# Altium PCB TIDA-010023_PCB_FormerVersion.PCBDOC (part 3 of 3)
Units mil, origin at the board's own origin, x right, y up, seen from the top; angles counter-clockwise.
Board outline 4724.44 x 3937.01 mil, 2 copper layers (Top Layer, Bottom Layer), stack 62 mil thick; 263 components, 126 nets, 611 pads, 186 vias.
Unrouted connection lines stored in the file: 58.
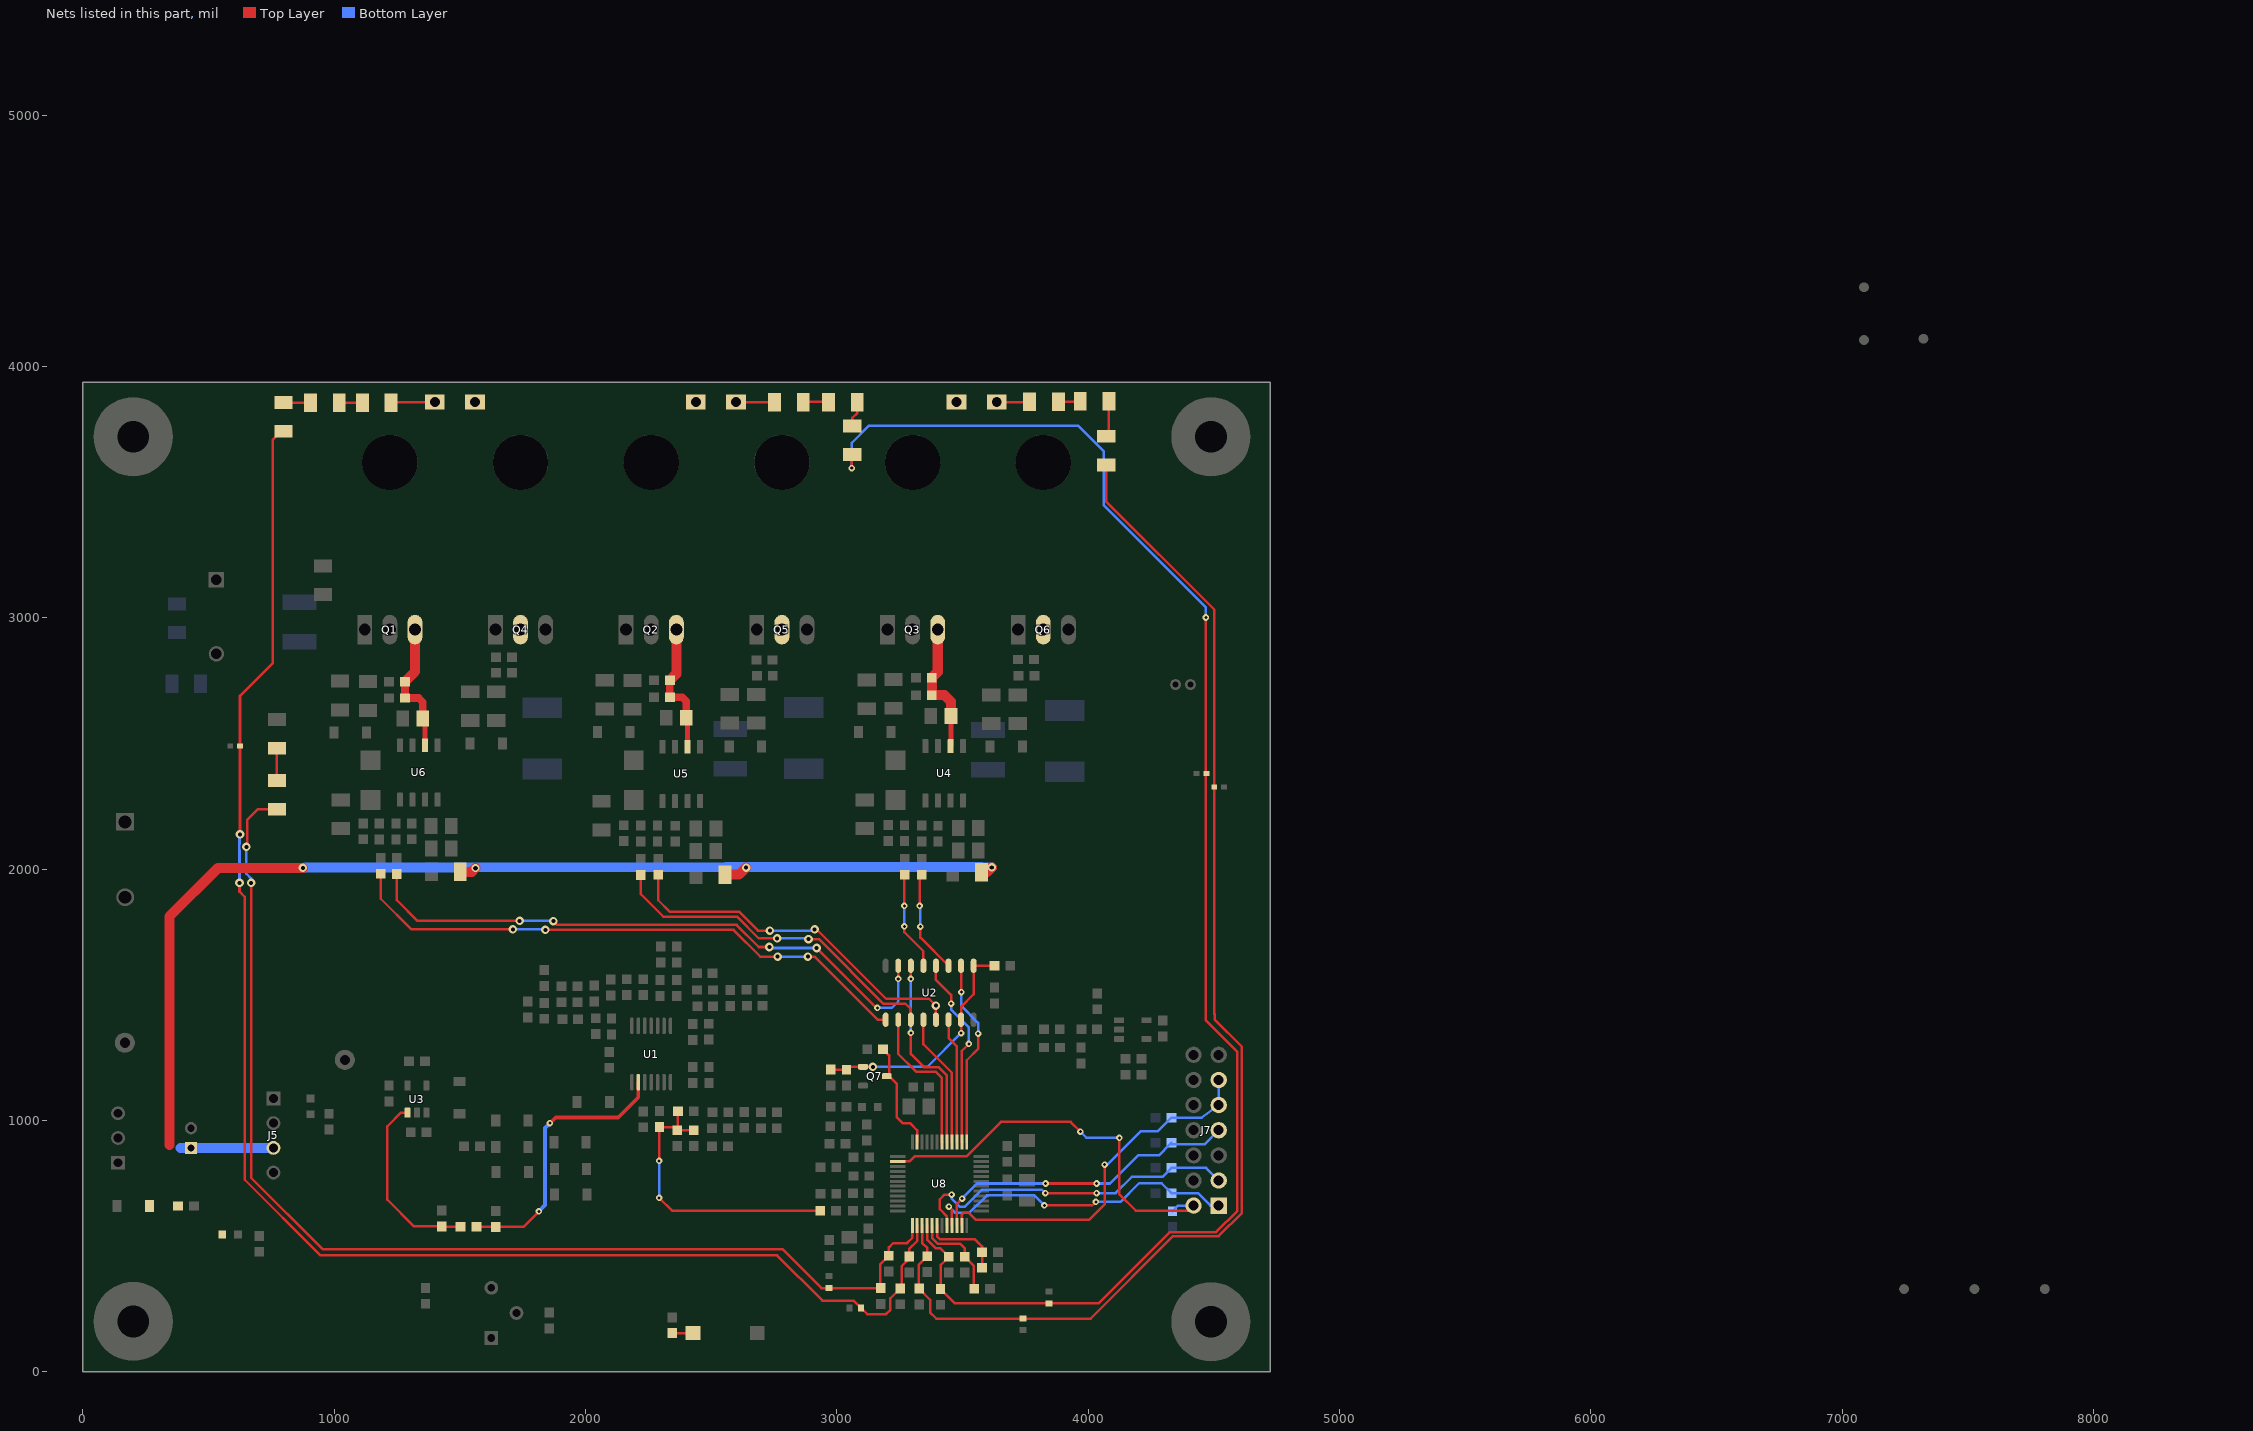
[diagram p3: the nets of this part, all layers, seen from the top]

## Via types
v1: diameter 26, hole 12, Top Layer to Bottom Layer, 157 vias
v2: diameter 34, hole 16, Top Layer to Bottom Layer, 28 vias
v3: diameter 32, hole 18, Top Layer to Bottom Layer, 1 vias

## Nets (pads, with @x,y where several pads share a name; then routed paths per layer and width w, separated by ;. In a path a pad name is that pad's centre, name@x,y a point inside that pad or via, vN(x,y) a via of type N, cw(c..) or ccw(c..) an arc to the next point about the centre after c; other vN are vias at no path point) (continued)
NetR92_1: R92.1 R96.2 | length 87.2
  Top Layer w10: R92.1@3881.09,3860 3966.91,3860 R96.2@3967.91,3861
NetR93_1: R93.1 R97.2 | length 100.8
  Top Layer w10: R93.1@2868.09,3859 R97.2@2968.91,3859
NetR94_1: R94.1 R98.2 | length 92.2
  Top Layer w10: R98.2@1021.09,3856 R94.1@1111.91,3856
  Top Layer w15: R98.2@1020.09,3855 R98.2@1021.09,3856
NetR95_1: R95.1 R105.2 | length 128.8
  Top Layer w10: R105.2@772,2352.09 R95.1@772,2480.91
NetR96_1: R96.1 R104.2 | length 145.5
  Top Layer w10: R96.1@4082.09,3861 4082.09,3726.17 4081,3725.09 R104.2@4090.09,3725.09
NetR97_1: R97.1 R106.2 | length 103.2
  Top Layer w10: R106.2@3061,3763.09 3061,3795 3081.09,3815.09 R97.1@3081.09,3858
NetR98_1: R98.1 R107.2 | length 108.4
  Top Layer w10: R107.2@799.09,3855 R98.1@905.91,3855
  Top Layer w15: R107.2@798,3856.09 R107.2@799.09,3855
OC: C9.1 Q7.1 R8.2 R118.2 U2.1 U2.15 | length 951.3
  Top Layer w10: R8.2@2975,1202.5 3037,1202.5 C9.1@3038,1201.5 3049.91,1213.4 Q7.1@3103.76,1213.4 v2(3143.4,1213.4) ; v1(3494,1347) U2.15@3494,1400.72 3494,1452 3544,1502 U2.1@3544,1615.28 3626.22,1615.28 R118.2@3626.5,1615
  Bottom Layer w10: v2(3143.4,1213.4) 3360.4,1213.4 v1(3494,1347)
OC_TZ: Q7.3 R119.2 U8.47 | length 456.2
  Top Layer w10: R119.2@3183.5,1283 3208,1258.5 3208,1185.76 Q7.3@3198.24,1176 3208,1176 3239,1145 3239,1012 3263,988 3292,988 3319.5,960.5 U8.47@3319.5,913.9
PHASE_A: C40.2 C41.2 J1.1 J1.2 Q1.3 Q4.2 R64.1 R94.2 U6.6 | length 713.4
  Top Layer w10: R94.2@1228.35,3858.27 J1.2@1400.16,3858.27
  Top Layer w20: C41.2@1352.52,2599.6 1361.52,2590.6 U6.6@1361.52,2492.87
  Top Layer w30: C40.2@1281.5,2745.7 R64.1@1281.5,2680.7 1336.3,2680.7 1352.52,2664.48 C41.2@1352.52,2599.6
  Top Layer w40: C40.2@1281.5,2745.7 1321.18,2785.39 Q1.3@1321.18,2952.76
PHASE_B: C33.2 C34.2 J2.1 J2.2 Q2.3 Q5.2 R49.1 R93.2 U5.6 | length 687.9
  Top Layer w10: J2.1@2598.43,3858.27 R93.2@2751.65,3858.27
  Top Layer w20: C34.2@2401,2602 2406,2597 U5.6@2406,2486.87
  Top Layer w30: R49.1@2335.5,2751 C33.2@2335.5,2683 2385,2683 2401,2667 C34.2@2401,2602
  Top Layer w40: R49.1@2335.5,2751 2361.18,2776.69 Q2.3@2361.18,2952.76
PHASE_C: C27.2 C28.2 J3.1 J3.2 Q3.3 Q6.2 R34.1 R92.2 U4.6 | length 667
  Top Layer w10: J3.1@3636,3858.27 R92.2@3765.18,3858.27
  Top Layer w15: R92.2@3765.18,3858.27 R92.2@3766.91,3860
  Top Layer w20: U4.6@3452,2489.27 3454,2491.27 C28.2@3454,2609
  Top Layer w40: Q3.3@3401.18,2952.76 3401.18,2784.69 C27.2@3377.5,2761 R34.1@3377.5,2692 3428,2692 3454,2666 C28.2@3454,2609
PWM_A_BOT: R65.1 U2.9 | length 2339.6
  Top Layer w10: R65.1@1185,1981.5 1185,1882 1307,1760 v2(1711,1760) ; v2(1840,1758) 2589,1758 2695,1652 v2(2764,1652) ; v2(2884,1652) 2911,1652 3162,1401 U2.9@3193.72,1401 ; U2.9@3190.72,1398 U2.9@3193.72,1401 ; U2.9@3194,1400.72 U2.9@3193.72,1401
  Bottom Layer w10: v2(1711,1760) 1838,1760 v2(1840,1758) ; v2(2764,1652) 2880,1652 2889,1643 2894,1648 2890,1652 v2(2884,1652)
PWM_A_TOP: R71.1 U2.7 | length 2430.4
  Top Layer w10: R71.1@1248,1979.5 R71.1@1249,1980.5 1249,1876 1331,1794 v2(1738,1794) ; v2(1872,1793) 1887,1778 2601,1778 2689,1690 v2(2731,1690) ; v2(2919,1686) 3157,1448 v1(3161,1448) ; v1(3244,1563) U2.7@3244,1615.28
  Bottom Layer w10: v2(1738,1794) 1871,1794 v2(1872,1793) ; v2(2731,1690) 2735,1686 v2(2919,1686) ; v1(3161,1448) 3218.3,1448 3244,1473.7 v1(3244,1563)
PWM_B_BOT: R50.1 U2.11 | length 1370.2
  Top Layer w10: R50.1@2220,1976.5 2220,1900 2309,1811 2602,1811 2689,1724 v2(2762,1724) ; v2(2887,1721) 2928,1721 3184,1465 3272,1465 3294,1443 U2.11@3294,1400.72
  Bottom Layer w10: v2(2762,1724) v2@2876.36,1724
PWM_B_TOP: R54.1 U2.13 | length 1449.1
  Top Layer w10: R54.1@2289,1977.5 2289,1876 2334,1831 2610,1831 2686,1755 v2(2733,1755) ; v2@2911,1768.63 v2(2911,1760) 2919.63,1760 3195.63,1484 3367,1484 v2(3394,1457) U2.13@3394,1400.72
  Bottom Layer w10: v2(2733,1755) 2906,1755 v2(2911,1760)
PWM_C_BOT: R35.1 U2.5 | length 394.5
  Top Layer w10: v1(3268,1772) 3268,1749 3344,1673 U2.5@3344,1615.28 ; v1(3268,1854) 3268,1975.5 R35.1@3270,1977.5
  Bottom Layer w10: v1(3268,1772) v1(3268,1854)
PWM_C_TOP: R36.1 U2.3 | length 413.2
  Top Layer w10: v1(3329,1854) 3329,1969.5 R36.1@3337,1977.5 ; v1(3332,1771) 3332,1727.28 U2.3@3444,1615.28
  Bottom Layer w10: v1(3329,1854) 3332,1851 v1(3332,1771)
RESET: R87.1 S1.1 | length 82.3
  Top Layer w10: R87.1@2345,153.5 2426.55,153.5 S1.1@2427.05,154
S_PWM_A_BOT: U2.10 U8.42 | length 606
  Top Layer w10: U2.10@3244,1400.72 3244,1265 3315,1194 3393,1194 3418,1169 U8.42@3418,913.9 U8.42@3419,914.9
S_PWM_A_TOP: U2.6 U8.41 | length 794.9
  Top Layer w10: v1(3294,1348) 3294,1264 3346,1212 3404,1212 3437.7,1178.3 U8.41@3437.7,913.9 ; v1(3294,1563) U2.6@3294,1615.28
  Bottom Layer w10: v1(3294,1348) v1(3294,1563)
S_PWM_B_BOT: U2.12 U8.40 | length 533.8
  Top Layer w10: U2.12@3344,1400.72 3344,1303 3457.4,1189.6 U8.40@3457.4,913.9
S_PWM_B_TOP: U2.14 U8.39 | length 500.5
  Top Layer w10: U2.14@3444,1400.72 3444,1328 3477.1,1294.9 U8.39@3477.1,913.9
S_PWM_C_BOT: U2.4 U8.38 | length 769
  Top Layer w10: U2.4@3394,1615.28 3394,1559 3454,1499 v1(3454,1465) ; U8.38@3498,915.1 U8.38@3496.8,913.9 3496.8,1276.8 v1(3525,1305)
  Bottom Layer w10: v1(3454,1465) 3454,1440.72 3525,1369.72 v1(3525,1305)
S_PWM_C_TOP: U2.2 U8.37 | length 748.4
  Top Layer w10: U2.2@3494,1615.28 3495,1614.28 v1(3495,1510) ; U8.37@3516.5,913.9 3516.5,1239.5 3562,1285 v1(3562,1345)
  Bottom Layer w10: v1(3495,1510) 3495,1455 3562,1388 v1(3562,1345)
Speed_Ref: C51.2 R79.2 U8.17 | length 372.1
  Top Layer w10: U8.17@3378.6,582 3378.6,532.4 3401,510 3489,510 3509,490 R79.2@3509,457.5 3544,422.5 3544,333.5 C51.2@3546.5,331
TCK: J7.9 J7.11 R102.1 U8.23 | length 1474.6
  Top Layer w10: U8.23@3496.8,582 3496.8,623.8 3506,633 3524,633 3553,604 4003,604 4065,666 v1(4065,824)
  Bottom Layer w10: v1(4065,824) 4076,824 4208,956 4275.89,956 R102.1@4330.89,1011 4452,1011 J7.9@4519,1061 ; J7.9@4502,1061 J7.9@4519,1061 ; J7.11@4519,1161 J7.9@4519,1061
TDI: J7.3 R100.1 U8.20 | length 1359.9
  Top Layer w10: U8.20@3437.7,582 3437.7,618.36 3409,647.06 3409,686 3428,705 v1(3456,705) ; v1(3829,711) v1(4033,711)
  Bottom Layer w10: v1(3456,705) 3456,689 3489,656 3508,656 3577,725 3815,725 v1(3829,711) ; v1(4033,711) 4109,711 4173,775 4294.89,775 R100.1@4330.89,811 4469,811 J7.3@4519,761
TDO: J7.7 R101.1 U8.22 | length 1256.2
  Top Layer w10: U8.22@3477.1,582 3477.1,668.1 v1(3498,689) ; v1(3830,749) v1(4033,749)
  Bottom Layer w10: v1(3498,689) 3558,749 v1(3830,749) ; v1(4033,749) 4086,749 4198,861 4280.89,861 R101.1@4326,906.11 ; R101.1@4330.89,911 R101.1@4326,906.11 ; J7.7@4519,961 4464.11,906.11 R101.1@4326,906.11
TEMP_SENSE: C44.2 R68.2 U8.18 | length 323.7
  Top Layer w10: U8.18@3398.3,582 3398.3,538.7 3409,528 3548,528 3577.5,498.5 C44.2@3577.5,475 R68.2@3577.5,414
TH+: R18.1 R19.2 U1.9 | length 1098
  Top Layer w10: R19.2@1565.5,577 1565.99,576.5 R18.1@1643,576.5 1752.5,576.5 v1(1814,638)
  Top Layer w15: v1(1858,989) 1881,1012 2130,1012 2209.8,1091.8 U1.9@2209.8,1152
  Bottom Layer w15: v1(1814,638) 1839,663 1839,970 v1(1858,989)
TH-: R19.1 R20.2 U3.1 | length 730.6
  Top Layer w10: U3.1@1291.6,1030.87 1265.87,1030.87 1211,976 1211,685 1317.5,578.5 R20.2@1428,578.5 1429.5,577 R19.1@1502.5,577
TMS: J7.1 R99.1 U8.21 | length 1282.5
  Top Layer w10: v1(3445,657) 3457.4,644.6 U8.21@3457.4,582 ; v1(3825.64,662) 4016,662 v1(4030,676)
  Bottom Layer w10: v1(3445,657) 3469,633 3527.79,633 3596.79,702 3785.64,702 v1(3825.64,662) ; v1(4030,676) 4128,676 4202,750 4291.89,750 R99.1@4330.89,711 4436,711 4486,661 J7.1@4519,661
TRST: J7.2 R103.1 U8.2 | length 1621.7
  Top Layer w10: U8.2@3242.1,836.7 3288.7,836.7 3309,857 3515,857 3652,994 3930,994 v1(3969,955) ; v1(4124,931) 4124,706 4189,641 4399,641 J7.2@4419,661
  Bottom Layer w10: v1(3969,955) 3993,931 v1(4124,931) ; R103.1@4335,638.5 4357.5,661 J7.2@4419,661
VA_FB: C64.1 D25.2 R107.1 R111.2 U8.14 U9.1 | length 6244.5
  Top Layer w10: v2(623,1945) 623,1910 644,1889 644,764 944,464 2122,464 2123,463 2762,463 2942,283 3066.62,283 D25.2@3096.62,253 3120.62,229 3196,229 3213,246 3213,292.5 R111.2@3252,331.5 ; v2(625,2138) 625,2689 755.46,2819.46 755.46,3708.46 788.91,3741.91 R107.1@798,3741.91 ; R111.2@3250,331.5 3257.3,338.8 3257.3,419.75 3287,449.45 C64.1@3287,458.5 3287,488 3319.5,520.5 U8.14@3319.5,582 U8.14@3320,581.5
  Bottom Layer w10: v2(623,1945) 623,2075.4 622,2076.4 622,2099.6 623,2100.6 623,2136 v2(625,2138)
VB_FB: C63.1 D24.2 R106.1 R110.2 U8.16 U10.1 | length 6140.2
  Top Layer w10: v1@3058,3594 v1(3059,3595) 3059,3646.91 R106.1@3061,3648.91 ; U8.16@3358.9,582 3358.9,526.1 3394,491 3411.5,491 C63.1@3445,457.5 3413,425.5 3413,330.5 R110.2@3412,329.5 3468.5,273 4042,273 4325,556 4509,556 4593,640 4593,1273 4468,1398 v1(4468,3001)
  Bottom Layer w10: v1(3059,3595) 3059,3696 3126,3763 3961,3763 4061,3663 4061,3448 4468,3041 v1(4468,3001)
VC_FB: C62.1 D23.2 R104.1 R109.2 U8.15 U11.1 | length 5012.5
  Top Layer w10: U8.15@3339.2,582 3339.2,512.8 3360,492 C62.1@3360,459.5 3325,424.5 3325,332.5 R109.2@3327,330.5 3371,286.5 3371,236 3396,211 4009,211 4338,540 4519,540 4611,632 4611,1293 4502.5,1401.5 4502.5,1423 4502.18,1423.32 4502.18,1485 4501.31,1485.87 U11.1@4501.31,2326 4501.31,3032.69 4071,3463 R104.1@4071,3607.91
VCC_15V: C59.1 C60.1 D18.2 D21.1 J5.3 R32.2 R42.2 R61.2 | length 4837.5
  Top Layer w40: 343.92,901.98 343.92,1810.92 538,2005 v2(875,2005) ; R61.2@1501.09,1989 1547,1989 v3(1562,2004) ; R42.2@2554.09,1978 2611,1978 v2(2639,2006) ; R32.2@3575.09,1987 3596,1987 v2(3616,2007)
  Bottom Layer w40: 387.76,890.24 C59.1@430,890.24 757.45,890.24 J5.3@758,890.79 ; v2@883,2006 1519,2006.71 1562,2006.76 2558,2007.87 2639,2007.96 3575,2009 3577,2007 v2(3616,2007)
VDC_FB: C61.1 D22.2 R105.1 R108.2 U8.13 | length 4592
  Top Layer w10: v2(650,2088) 653,2091 653,2196 694.91,2237.91 R105.1@772,2237.91 ; v2(669,1945) 669,772 953.34,487.66 2783.34,487.66 2938.5,332.5 R108.2@3174,332.5 3172,334.5 3172,426.5 C61.1@3207,461.5 3207,495 3224,512 3279,512 3299.8,532.8 U8.13@3299.8,582
  Bottom Layer w10: v2(650,2088) 650,1982 669,1963 v2(669,1945)
VREF: C18.1 R23.1 R24.2 R25.1 R120.1 | length 1163.5
  Top Layer w10: v1(2293,692) 2345,640 R120.1@2933.5,640 ; v1(2293,839.33) 2293,972.72 R23.1@2293.98,973.7 2356.98,973.7 C18.1@2367.49,963.2 ; R25.1@2367.49,1036.2 C18.1@2367.49,963.2 ; R24.2@2429.98,960.7 C18.1@2364.98,960.7 C18.1@2367.49,963.2
  Bottom Layer w10: v1(2293,692) v1(2293,839.33)
pads on no net: FID1.1 FID2.1 FID3.1 FID4.1 FID5.1 FID6.1 H1.1 H2.1 H3.1 H4.1 H11.0 H12.0 H13.0 H14.0 J5.4 J6.3 J7.6 J7.13 J7.14 U8.1 U8.4 U8.8 U8.9 U8.19 U8.24 U8.25 U8.26 U8.27 U8.28 U8.29 U8.30 U8.31 U8.36 U8.45 U8.46

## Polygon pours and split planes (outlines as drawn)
PHASE_C on Top Layer "TOP_LAYER_PHASE_C_P062" (solid, remove dead copper, pour order 62): 3388,2900 3420,2900 3539,2900 3554,2915 3554,3124 3579,3149 3751,3149 3791,3109 3791,2916 3810,2897 3833,2897 3850,2914 3850,3322 3849,3322 3678,3493 3680,3495 3680,3887 3438,3887 3437,3886 3437,3054 3371,2988 3371,2917
PHASE_B on Top Layer "TOP_LAYER_PHASE_B_P060" (solid, remove dead copper, pour order 60): 2348,2903 2380,2903 2499,2903 2514,2918 2514,3127 2539,3152 2711,3152 2751,3112 2751,2919 2770,2900 2793,2900 2810,2917 2810,3325 2809,3325 2638,3496 2640,3498 2640,3890 2398,3890 2397,3889 2397,3057 2331,2991 2331,2920
PHASE_A on Top Layer "TOP_LAYER_PHASE_A_P058" (solid, remove dead copper, pour order 58): 1309,2901 1341,2901 1460,2901 1475,2916 1475,3125 1500,3150 1672,3150 1712,3110 1712,2917 1731,2898 1754,2898 1771,2915 1771,3323 1770,3323 1599,3494 1601,3496 1601,3888 1359,3888 1358,3887 1358,3055 1292,2989 1292,2918
VCC_15V on Top Layer "Top Layer-No Net 2" (solid, pour order 44): 459.19,914.69 459.19,772.19 397,710 397,633.69 348.61,633.69 246.19,633.69 246.19,894.69 266.19,914.69
PHASE_A on Top Layer "Top Layer-No Net 1" (solid, pour order 36): 1587,3507 1771,3323 1771,3161 1760,3161 1587,3334
NetQ6_3 on Bottom Layer "BOTTOM_LAYER_NETQ6_3_P078" (solid, remove dead copper, pour order 78): 3828,2590 3986,2590 4014,2618 4013.82,2984.18 3999,2999 3911,2999 3891,2979 3891,2805 3828,2742
NetQ5_3 on Bottom Layer "BOTTOM_LAYER_NETQ5_3_P076" (solid, remove dead copper, pour order 76): 2789,2601 2947,2601 2975,2629 2974.82,2995.18 2960,3010 2872,3010 2852,2990 2852,2816 2789,2753
+VDC on Bottom Layer "Bottom Layer-No Net 2" (solid, remove dead copper, pour order 74): 101,2153 232,2153 246,2167 246,2955 321,3030 931,3030 1027,3126 1027,3166 1053,3192 1153,3192 1195,3150 1250,3150 1288,3188 2189,3188 2232,3145 2291,3145 2330,3184 2488,3184 2501,3171 2541,3171 2554,3184 3222,3184 3270,3136 3330,3136 3383,3189 3508,3189 3533,3164 3573,3164 3593,3184 3593,3392 3571,3414 507,3414 429,3336 429,3335 209,3335 88,3214 87,3214 87,2167
AGND on Bottom Layer "Bottom Layer-No Net 2" (solid, remove dead copper, pour order 70): 84,1800 96,1788 380,1788 536,1944 536,2381 573,2418 705,2418 982,2141 3912.16,2141 3999,2227.84 3999,2417 3986,2430 3824,2430 3789,2395 3699.93,2395 3666.93,2428 3534.07,2428 3502,2395.93 3502,2395 2993,2395 2946,2442 2791,2442 2744,2395 2677.93,2395 2641.93,2431 2641.93,2432 2508.07,2432 2508.07,2431.07 2472,2395 1951,2395 1905,2441 1749,2441 1703,2395 1159,2395 928.93,2625.07 928.93,2940.07 914,2951 910,2951 551,2951 442.45,2842.45 442.45,2664 358,2579.55 358,2043 305,1990 95,1990 84,1979
NetQ4_3 on Bottom Layer "BOTTOM_LAYER_NETQ4_3_P066" (solid, remove dead copper, pour order 66): 1749,2601 1907,2601 1935,2629 1934.82,2995.18 1920,3010 1832,3010 1812,2990 1812,2816 1749,2753

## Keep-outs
Keep-Out Layer:
  circle w10: c200,3720.47 r293.13
  circle w10: c4488.19,3720.47 r315.73
  circle w10: c4488.19,199 r305.93
  circle w10: c204,193 r375.59
  text ".Layer_Name" at 577,-858.49 h60

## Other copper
Top Layer:
  rectangle net NetD21_2: 51,634 167,860
  text ".Layer_Name" at 577,-858.49 h60
Bottom Layer:
  pour cut-out: 2946,2602 2946,2603 2977.82,2634.82 2977.82,2602
  pour cut-out: 910,2951 918,2951 914,2955
  text ".Layer_Name" at 577,-858.49 h60

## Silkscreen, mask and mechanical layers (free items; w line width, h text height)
Top Overlay:
  region: 982,185 682,185 682,85 982,85
  lines w10: 834,1921 1004,1921 1087.8,2090.02 ; 1751,1355 1876.02,1442.8 ; 1870,1924 2053,1924 2124.1,2083.02 ; 2244,1669 2268.78,1587.18 ; 2390.27,1586.98 2416,1658 ; 2520,1426 2532,1412 ; 2534.98,1546.2 2563,1660 ; 2594.96,993 2601,1120 ; 2937,1925 3118,1925 3176.8,2084.02
  text "TIDA-010023.PCB_Rev-1" at 513,213 h78.74
  text ".Layer_Name" at 577,-858.49 h60
Bottom Overlay:
  text ".Layer_Name" at 577,-858.49 h60
Top Paste:
  text ".Layer_Name" at 577,-858.49 h60
Bottom Paste:
  text ".Layer_Name" at 577,-858.49 h60
Top Solder:
  text ".Layer_Name" at 577,-858.49 h60
  text ".Layer_Name" at 577,-858.49 h60
Bottom Solder:
  region: 84,1800 96,1788 380,1788 536,1944 536,2381 573,2418 705,2418 982,2141 3912.16,2141 3999,2227.84 3999,2417 3986,2430 3824,2430 3789,2395 3699.93,2395 3666.93,2428 3534.07,2428 3534.07,2427.07 3502,2395 1159,2395 928.93,2625.07 928.93,2940.07 918,2951 551,2951 442.45,2842.45 442.45,2664 358,2579.55 358,2043 305,1990 95,1990 84,1979
  region: 3270,2952 3331,2952 3331,3135 3385,3189 3219,3189 3271,3137 3271,2951
  region: 2231,2950 2292,2950 2292,3144 2291,3145 2341,3195 2341,3213 2189,3213 2187,3211 2189,3209 2189,3188 2232,3145 2231,3144
  region: 1190,2949 1252,2949 1250,2951 1250,3150 1288,3188 1288,3231 1154,3231 1156,3229 1156,3188 1191,3153 1190,3152
  region: 87,2167 101,2153 232,2153 246,2167 246,2955 321,3030 931,3030 1027,3126 1027,3166 1050,3189 1056,3189 3593,3189 3593,3392 3571,3414 507,3414 429,3336 429,3335 209,3335 88,3214 87,3214
  text ".Layer_Name" at 577,-858.49 h60
Drill Guide:
  text ".Layer_Name" at 577,-858.49 h60
M1 Board Outline:
  the board outline again, w10
  text ".Layer_Name" at 577,-858.49 h60
M2 Board Dimensions:
  rectangle: 125,-400 500,-275
  rectangle: 0,-275 125,-150
  lines w7: 0,-275 1000,-275 ; 125,-400 125,-150 ; 250,-400 250,-150 ; 500,-400 500,-150 ; 750,-400 750,-150 ; 0,-400 0,-150 1000,-150 1000,-400 0,-400
  text ".Layer_Name" at 577,-858.49 h60
M3 3D STEP Top:
  text ".Layer_Name" at 577,-858.49 h60
M4 3D STEP Bottom:
  text ".Layer_Name" at 577,-858.49 h60
M5 Assembly Top:
  lines w10: -292,-930.17 6308,-930.17 ; -292,-726.83 6310,-726.83 ; -292,-523.5 -292,-1133.5 3713,-1133.5 6310,-1133.5 6310,-523.5 -291.5,-523.5 -291.5,-1133.5 1284,-1133.5 ; 2173,-1133.5 2173,-523.5 ; 3440,-726.83 3440,-523.5 ; 4280,-726.83 4280,-523.5 ; 4902,-1140 4902,-937.17
  text "COMPONENTS MARKED 'DNP' SHOULD NOT BE POPULATED." at 1153.5,-318.5 h60
  text "ASSEMBLY VARIANT:" at 1153,-434 h60
  text ".VariantName" at 2189,-434 h60
  text "PCB VIEWED FROM TOP SIDE" at -228.5,-655.67 h60
  text "BOARD #:" at 2248,-655.67 h60
  text ".PRJ_Number" at 2793.5,-655.67 h60
  text "REV:" at 3638,-655.67 h60
  text ".PCB_Rev" at 3929.5,-655.67 h60
  text "SVN REV:" at 4476,-655.67 h60
  text ".VersionControl_RevNumber" at 4982,-655.67 h60
  text "TID #:" at 2248,-859 h60
  text ".TID" at 2793.5,-859 h60
  text "PLOT NAME =" at -228.5,-1064.34 h60
  text ".plot_File_Name" at 577,-1064.34 h60
  text "GENERATED    :" at 2250,-1064.34 h60
  text ".Print_Date" at 3119.5,-1064.34 h60
  text ".Print_Time" at 3848.5,-1064.34 h60
  text "TEXAS INSTRUMENTS" at 5113,-1064.34 h60
M6 Assembly Bottom:
  lines w10: -292.5,-727.33 6309.5,-727.33 ; -290.5,-930.67 6309.5,-930.67 ; 1115.5,-1140.5 1115.5,-937.67 ; 1737.5,-727.33 1737.5,-524 ; 2577.5,-727.33 2577.5,-524 ; 3844.5,-1134 3844.5,-524 ; 4733.5,-1134 6309,-1134 6309,-524 -292.5,-524 -292.5,-1134 2304.5,-1134 6309.5,-1134 6309.5,-524
  text "COMPONENTS MARKED 'DNP' SHOULD NOT BE POPULATED." at 6102,-318 h60
  text ".VariantName" at 5058,-434 h60
  text "ASSEMBLY VARIANT:" at 6097,-434 h60
  text ".VersionControl_RevNumber" at 1035.5,-656.17 h60
  text "SVN REV:" at 1541.5,-656.17 h60
  text ".PCB_Rev" at 2088,-656.17 h60
  text "REV:" at 2379.5,-656.17 h60
  text ".PRJ_Number" at 3224,-656.17 h60
  text "BOARD #:" at 3769.5,-656.17 h60
  text "PCB VIEWED FROM BOTTOM SIDE" at 6246,-656.17 h60
  text ".TID" at 3224,-859.5 h60
  text "TID #:" at 3769.5,-859.5 h60
  text "TEXAS INSTRUMENTS" at 904.5,-1064.84 h60
  text ".Print_Time" at 2169,-1064.84 h60
  text ".Print_Date" at 2898,-1064.84 h60
  text "GENERATED    :" at 3767.5,-1064.84 h60
  text ".plot_File_Name" at 5440.5,-1064.84 h60
  text "PLOT NAME =" at 6246,-1064.84 h60
M9 Title Sheet:
  drawing of 57 lines, arcs and shapes, not listed
  text "1" at 739.84,8036.5 h70
  text "2" at 3235.5,8036.5 h70
  text "3" at 5724.84,8036.5 h70
  text "4" at 8231.51,8036.5 h70
  text "5" at 10730.5,8036.5 h70
  text "6" at 13235.5,8036.5 h70
  text "A" at -416.5,6893.5 h70
  text "A" at 14383.5,6893.5 h70
  text "B" at -416.5,4513.5 h70
  text "B" at 14383.5,4513.5 h70
  text "C" at -416.5,2138.5 h70
  text "C" at 14383.5,2138.5 h70
  text "PROJECT TITLE:" at 11343.5,277.5 h45
  text ".PRJ_Title" at 11393.5,144.17 h70
  text "DESIGNED FOR:" at 11343.5,-23.5 h45
  text ".PRJ_Customer" at 11393.5,-163.5 h70
  text "D" at -416.5,-231.5 h70
  text "D" at 14383.5,-231.5 h70
  text "FILE NAME:" at 11343.5,-323.5 h45
  text ".PCB_File_Name_No_Path" at 11393.5,-443.5 h70
  text "Texas Instruments (TI) and/or its licensors do not warrant the accuracy or completeness of this specification" at 6374,-605.34 h45
  text "ENGINEER:" at 11343.5,-613.5 h45
  text "LAYOUT BY:" at 12848.5,-613.5 h45
  text "or any information contained therein. TI and/or its licensors do not warrant that this design will meet" at 6329.01,-718 h45
  text ".PRJ_Engineer" at 11393.5,-768.49 h70
  text ".PCB_Layout" at 12899,-768.49 h70
  text "the specifications, will be suitable for your application or fit for any particular purpose, or will operate in" at 6329.01,-830.67 h45
  text ".Layer_Name" at 577,-858.49 h60
  text "ALTIUM DESIGNER VERSION:" at 12848.5,-923.5 h45
  text "an implementation. TI and/or its licensors do not warrant that the design is production worthy. You should" at 6329.01,-943.33 h45
  text "completely validate and test your design implementation to confirm the system functionality for your application." at 6374,-1056 h45
  text ".print_Scale" at 11393.5,-1056.83 h70
  text ".Application_BuildNumber" at 12899,-1056.83 h70
  text "1" at 739.84,-1263.5 h70
  text "2" at 3235.5,-1263.5 h70
  text "3" at 5724.84,-1263.5 h70
  text "4" at 8231.51,-1263.5 h70
  text "5" at 10730.5,-1263.5 h70
  text "6" at 13235.5,-1263.5 h70
M10 Fab Notes:
  drawing of 189 lines, arcs and shapes, not listed
  text "DESIGN INFORMATION" at 12382.02,6356.17 h60
  text "MIN. TRACK WIDTH:" at 11737.46,6224.05 h60
  text "8" at 12833.7,6224.05 h60
  text "MIL" at 12988.46,6224.05 h60
  text "MIN. CLEARANCE:" at 11737.46,6099.92 h60
  text "0.2" at 12773.7,6099.93 h60
  text "mm" at 12988.46,6099.92 h60
  text "MIN. VIA PAD SIZE:" at 11737.46,5975.8 h60
  text "24" at 12803.71,5975.8 h60
  text "MIL" at 12988.46,5975.8 h60
  text "0.05mm (2MIL)" at 12432.46,5845.9 h60
  text "MINIMUM ANNULAR RING" at 11408.23,5837.67 h60
  text "EXTERNAL" at 13140.46,5837.67 h60
  text "PER" at 11608.23,5727.55 h60
  text "IPC-D-275 CLASS 2 LEVEL C" at 11828.23,5727.54 h60
  text "MIL, HOLES" at 13316.46,5627.07 h60
  text "+/-" at 12924,5618.48 h60
  text "+/-" at 13778,5618.48 h60
  text "REGISTRATION TOLERANCES:" at 11408.23,5617.42 h60
  text "METAL" at 12608,5617.42 h60
  text "5" at 13184.2,5617.42 h60
  text "3" at 14017.2,5617.42 h60
  text "MIL" at 14133.46,5617.42 h60
  text "HOLE SIZE TOLERANCE (UNLESS OTHERWISE SPECIFIED):" at 11408.23,5519.1 h60
  text "+/-" at 13778,5516.23 h60
  text "3" at 14017.2,5515.17 h60
  text "MIL" at 14133.46,5515.17 h60
  text "MATERIAL:" at 11333.46,5377.52 h60
  text "FR-4 High Tg" at 12319.9,5249 h60
  text "X" at 12175.46,5241.01 h60
  text "FR-408" at 11754.46,5236.49 h60
  text "OTHER" at 13242.46,5236.49 h60
  text "62 MIL (1.6mm) +/-10%" at 12074.56,5093.46 h60
  text "X" at 11954.46,5091.01 h60
  text "THICKNESS:" at 11408.23,5085.24 h60
  text "OTHER" at 13359.46,5085.24 h60
  text "TOLERANCE:" at 11408.23,4946.92 h60
  text "X" at 12256.46,4946.92 h60
  text "ANSI IPC-6012 TYPE 3 CLASS 2" at 12434.48,4946.92 h60
  text "OTHER +/-" at 12434.46,4802.73 h60
  text "BOW & TWIST:" at 11408.23,4657.54 h60
  text "X" at 12256.46,4657.54 h60
  text "ANSI IPC-6012 TYPE 3 CLASS 2" at 12434.48,4657.54 h60
  text "OTHER +/-" at 12434.46,4510.85 h60
  text "DRILLING:" at 11333.46,4380.23 h60
  text "NC_DRILL FILES" at 13094.46,4275.04 h60
  text "REFERENCE:" at 11408.23,4271.1 h60
  text "X" at 12065.46,4271.01 h60
  text "AS SHOWN" at 12243.46,4271.1 h60
  text "X" at 12966.46,4271.1 h60
  text "OTHER" at 13392.46,4128.85 h60
  text "PTH COPPER THICKNESS:" at 11407.91,4125.32 h60
  text "X" at 12547.14,4125.32 h60
  text "20-30 um" at 12675.14,4125.32 h60
  text "BOARD FINISH:" at 11333.46,3977.73 h60
  text "SILKSCREEN:" at 11488.68,3867.6 h60
  text "X" at 12446.46,3867.6 h60
  text "TOP" at 12563.46,3867.6 h60
  text "X" at 12956.46,3867.6 h60
  text "BOTTOM" at 13074.46,3867.6 h60
  text "SILKSCREEN COLOR:" at 11488.68,3712.41 h60
  text "X" at 12445.46,3712.41 h60
  text "WHITE" at 12563.46,3712.41 h60
  text "OTHER" at 13074.46,3712.41 h60
  text "X" at 12576.46,3568.96 h60
  text "GREEN" at 12694.46,3568.96 h60
  text "OTHER" at 13312.46,3568.96 h60
  text "SOLDER RESIST COLOR:" at 11488.68,3562.1 h60
  text "X" at 12576.46,3414.71 h60
  text "MATTE" at 12694.46,3414.71 h60
  text "SEMI-GLOSS" at 13312,3414.07 h60
  text "IMMERSION GOLD (ENIG)" at 12394.46,3241.94 h60
  text "ENEPIG" at 13732,3234.72 h60
  text "SURFACE FINISH:" at 11333.46,3233.72 h60
  text "X" at 12216.46,3233.72 h60
  text "IMM. TIN/SILVER OR EQUIV" at 11663,3096.4 h60
  text "OTHER" at 13094.46,3092.47 h60
  text "ARRAY/PANEL:" at 11333.46,2937.09 h60
  text "CUT AND TRIM PER M1 BOARD OUTLINE" at 12394.46,2928.87 h60
  text "N.C. ROUTE" at 12394.46,2792.9 h60
  text "X" at 13082.46,2792.9 h60
  text "V. SCORE" at 13260.46,2792.9 h60
  text "CERTIFICATION:" at 11333.46,2663.77 h60
  text "MATERIALS AND WORKMANSHIP FOR ALL PCBS" at 12058.46,2663.77 h60
  text "TO MEET OR EXCEED THE REQUIREMENTS OF:" at 12058.46,2569.71 h60
  text "X" at 11695.97,2441.08 h60
  text "ANSI IPC-A-600F CLASS ->" at 11823.96,2441.08 h60
  text "X" at 13471.97,2441.08 h60
  text "2" at 13581.96,2441.08 h60
  text "1" at 13266.96,2439.58 h60
  text "3" at 13935.96,2439.58 h60
  text "X" at 12507.97,2293.39 h60
  text "RoHS" at 12635.96,2293.39 h60
  text "OTHER" at 13280.36,2293.39 h60
  text "PER ORDER" at 13677.42,2293.39 h60
  text "ALL BOARDS MUST MEET OR EXCEED UL94-V0 REQUIREMENTS." at 11361,2139.57 h60
  text "PCB MUST BEAR THE UL94V-0 UL REGISTERED MATERIAL ID NUMBER" at 11361,2023.5 h60
  text "ADDITIONAL REQUIREMENTS:" at 11333.46,1854.08 h60
  text "MICROSECTION:" at 11408.23,1746.95 h60
  text "YES" at 12313.96,1746.95 h60
  text "REQUIRED" at 13175.46,1602.62 h60
  text "BARE BOARD ELEC. TEST:" at 11408.23,1599.76 h60
  text "NONE" at 12713.96,1599.76 h60
  text "X" at 13057.46,1599.76 h60
  text "PER ORDER" at 13767.46,1599.76 h60
  text "XX MIL VIAS REQUIRE NON-CONDUCTIVE FILL AND PLANARIZE" at 11576.38,1394.82 h59
  text "XX MIL VIAS REQUIRE CONDUCTIVE FILL AND PLANARIZE" at 11584.38,1290.84 h60
  text "OUTER XX MIL VIAS REQUIRE 50 OHM SINGLE-ENDED IMPEDANCE" at 11583.39,1127.46 h58
  text "LAYER 2 & 3 (INNER LAYERS) XX MIL WIDE, XX MIL SPACE / TRACES REQUIRE 100 OHM DIFFERENTIAL IMPEDANCE" at 11575.39,891.74 h60
  text ".Layer_Name" at 577,-858.49 h60
M11 Gerber Information:
  lines w10: -292,-930.17 6308,-930.17 ; -292,-726.83 6310,-726.83 ; -292,-523.5 -292,-1133.5 3713,-1133.5 6310,-1133.5 6310,-523.5 -291.5,-523.5 -291.5,-1133.5 1284,-1133.5 ; 2173,-1133.5 2173,-523.5 ; 3440,-726.83 3440,-523.5 ; 4280,-726.83 4280,-523.5 ; 4902,-1140 4902,-937.17
  text "ALL ARTWORK VIEWED FROM TOP SIDE" at -228.5,-655.67 h60
  text "BOARD #:" at 2248,-655.67 h60
  text ".PRJ_Number" at 2793.5,-655.67 h60
  text "REV:" at 3638,-655.67 h60
  text ".PCB_Rev" at 3929.5,-655.67 h60
  text "SVN REV:" at 4476,-655.67 h60
  text ".VersionControl_RevNumber" at 4982,-655.67 h60
  text "LAYER NAME =" at -228.5,-858.49 h60
  text "TID #:" at 2248,-859 h60
  text ".TID" at 2793.5,-859 h60
  text "PLOT NAME =" at -228.5,-1064.34 h60
  text ".plot_File_Name" at 577,-1064.34 h60
  text "GENERATED    :" at 2250,-1064.34 h60
  text ".Print_Date" at 3119.5,-1064.34 h60
  text ".Print_Time" at 3848.5,-1064.34 h60
  text "TEXAS INSTRUMENTS" at 5113,-1064.34 h60
M12 Stackup:
  drawing of 191 lines, arcs and shapes, not listed
  text "Layer" at 9797.84,7830 h60
  text "Name" at 10207.76,7830 h60
  text "Material" at 11137.5,7830 h60
  text "Thickness" at 11997.27,7830 h60
  text "Constant" at 12647.1,7830 h60
  text "Board Layer Stack" at 13216.96,7830 h60
  text "1" at 9797.84,7710 h60
  text "Top Overlay" at 10207.76,7710 h60
  text "2" at 9797.84,7590 h60
  text "Top Solder" at 10207.76,7590 h60
  text "Solder Resist" at 11137.5,7590 h60
  text "0.40mil" at 11997.27,7590 h60
  text "3.5" at 12647.1,7590 h60
  text "3" at 9797.84,7470 h60
  text "Top Layer" at 10207.76,7470 h60
  text "Copper" at 11137.5,7470 h60
  text "1.40mil" at 11997.27,7470 h60
  text "4" at 9797.84,7350 h60
  text "Dielectric1" at 10207.76,7350 h60
  text "FR-4" at 11137.5,7350 h60
  text "59.20mil" at 11997.27,7350 h60
  text "4.8" at 12647.1,7350 h60
  text "5" at 9797.84,7230 h60
  text "Bottom Layer" at 10207.76,7230 h60
  text "Copper" at 11137.5,7230 h60
  text "1.40mil" at 11997.27,7230 h60
  text "6" at 9797.84,7110 h60
  text "Bottom Solder" at 10207.76,7110 h60
  text "Solder Resist" at 11137.5,7110 h60
  text "0.40mil" at 11997.27,7110 h60
  text "3.5" at 12647.1,7110 h60
  text "7" at 9797.84,6990 h60
  text "Bottom Overlay" at 10207.76,6990 h60
  text ".Layer_Name" at 577,-858.49 h60
M13 Component Bodies Top:
  text ".Layer_Name" at 577,-858.49 h60
M14 Component Bodies Bottom:
  text ".Layer_Name" at 577,-858.49 h60
M15 Courtyards Top:
  text ".Layer_Name" at 577,-858.49 h60
M16 Courtyards Bottom:
  text ".Layer_Name" at 577,-858.49 h60
Drill Drawing:
  drawing of 160 lines, arcs and shapes, not listed
  text "Symbol" at 5345.59,3385.75 h72
  text "Quantity" at 5631.28,3385.75 h72
  text "Finished Hole Size" at 5948.38,3385.75 h72
  text "Plated" at 6570.02,3385.75 h72
  text "Hole Type" at 6814.21,3385.75 h72
  text "Drill Layer Pair" at 7174.45,3385.75 h72
  text "Hole Tolerance" at 7882.92,3385.75 h72
  text "157" at 5631.28,3286.43 h60
  text "12.00mil (0.305mm)" at 5948.38,3286.43 h60
  text "PTH" at 6570.02,3286.43 h60
  text "Round" at 6814.21,3286.43 h60
  text "Top Layer - Bottom Layer" at 7174.45,3286.43 h60
  text "28" at 5631.28,3187.11 h60
  text "16.00mil (0.406mm)" at 5948.38,3187.11 h60
  text "PTH" at 6570.02,3187.11 h60
  text "Round" at 6814.21,3187.11 h60
  text "Top Layer - Bottom Layer" at 7174.45,3187.11 h60
  text "1" at 5631.28,3087.79 h60
  text "18.00mil (0.457mm)" at 5948.38,3087.79 h60
  text "PTH" at 6570.02,3087.79 h60
  text "Round" at 6814.21,3087.79 h60
  text "Top Layer - Bottom Layer" at 7174.45,3087.79 h60
  text "2" at 5631.28,2988.47 h60
  text "23.62mil (0.600mm)" at 5948.38,2988.47 h60
  text "PTH" at 6570.02,2988.47 h60
  text "Round" at 6814.21,2988.47 h60
  text "Top Layer - Bottom Layer" at 7174.45,2988.47 h60
  text "2" at 5631.28,2889.15 h60
  text "29.53mil (0.750mm)" at 5948.38,2889.15 h60
  text "PTH" at 6570.02,2889.15 h60
  text "Round" at 6814.21,2889.15 h60
  text "Top Layer - Bottom Layer" at 7174.45,2889.15 h60
  text "3" at 5631.28,2789.83 h60
  text "31.00mil (0.787mm)" at 5948.38,2789.83 h60
  text "PTH" at 6570.02,2789.83 h60
  text "Round" at 6814.21,2789.83 h60
  text "Top Layer - Bottom Layer" at 7174.45,2789.83 h60
  text "7" at 5631.28,2690.51 h60
  text "35.43mil (0.900mm)" at 5948.38,2690.51 h60
  text "PTH" at 6570.02,2690.51 h60
  text "Round" at 6814.21,2690.51 h60
  text "Top Layer - Bottom Layer" at 7174.45,2690.51 h60
  text "16" at 5631.28,2591.19 h60
  text "40.00mil (1.016mm)" at 5948.38,2591.19 h60
  text "PTH" at 6570.02,2591.19 h60
  text "Round" at 6814.21,2591.19 h60
  text "Top Layer - Bottom Layer" at 7174.45,2591.19 h60
  text "2" at 5631.28,2491.87 h60
  text "41.34mil (1.050mm)" at 5948.38,2491.87 h60
  text "PTH" at 6570.02,2491.87 h60
  text "Round" at 6814.21,2491.87 h60
  text "Top Layer - Bottom Layer" at 7174.45,2491.87 h60
  text "18" at 5631.28,2392.55 h60
  text "47.24mil (1.200mm)" at 5948.38,2392.55 h60
  text "PTH" at 6570.02,2392.55 h60
  text "Round" at 6814.21,2392.55 h60
  text "Top Layer - Bottom Layer" at 7174.45,2392.55 h60
  text "2" at 5631.28,2293.23 h60
  text "51.18mil (1.300mm)" at 5948.38,2293.23 h60
  text "PTH" at 6570.02,2293.23 h60
  text "Round" at 6814.21,2293.23 h60
  text "Top Layer - Bottom Layer" at 7174.45,2293.23 h60
  text "4" at 5631.28,2193.91 h60
  text "125.98mil (3.200mm)" at 5948.38,2193.91 h60
  text "PTH" at 6570.02,2193.91 h60
  text "Round" at 6814.21,2193.91 h60
  text "Top Layer - Bottom Layer" at 7174.45,2193.91 h60
  text "6" at 5631.28,2094.59 h60
  text "220.00mil (5.588mm)" at 5948.38,2094.59 h60
  text "PTH" at 6570.02,2094.59 h60
  text "Round" at 6814.21,2094.59 h60
  text "Top Layer - Bottom Layer" at 7174.45,2094.59 h60
  text "6" at 5631.28,1995.27 h60
  text "39.37mil (1.000mm)" at 5948.38,1995.27 h60
  text "PTH" at 6570.02,1995.27 h60
  text "Rectangle" at 6814.21,1995.27 h60
  text "Top Layer - Bottom Layer" at 7174.45,1995.27 h60
  text "254 Total" at 5631.28,1895.95 h60
  text "Slot definitions :" at 5345.59,1816.48 h60
  text "Routed Path Length" at 5788.14,1816.48 h60
  text "= Calculated from tool start centre position to tool end centre position." at 6319.59,1816.48 h60
  text "Hole Length" at 5788.14,1766.81 h60
  text "= Routed Path Length + Tool Size = Slot length as defined in the PCB layout" at 6120.08,1766.81 h60
  text ".Layer_Name" at 577,-858.49 h60
M17 Embedded Cavity:
  text ".Layer_Name" at 577,-858.49 h60
M18 Embedded Assembly:
  text ".Layer_Name" at 577,-858.49 h60
M19 Embedded Keepout:
  text ".Layer_Name" at 577,-858.49 h60

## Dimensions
0,3937.01 to 0,0 on M2 Board Dimensions
0,0 to 4724.44,0 on M2 Board Dimensions
0,-400 to 1000,-400 on M2 Board Dimensions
